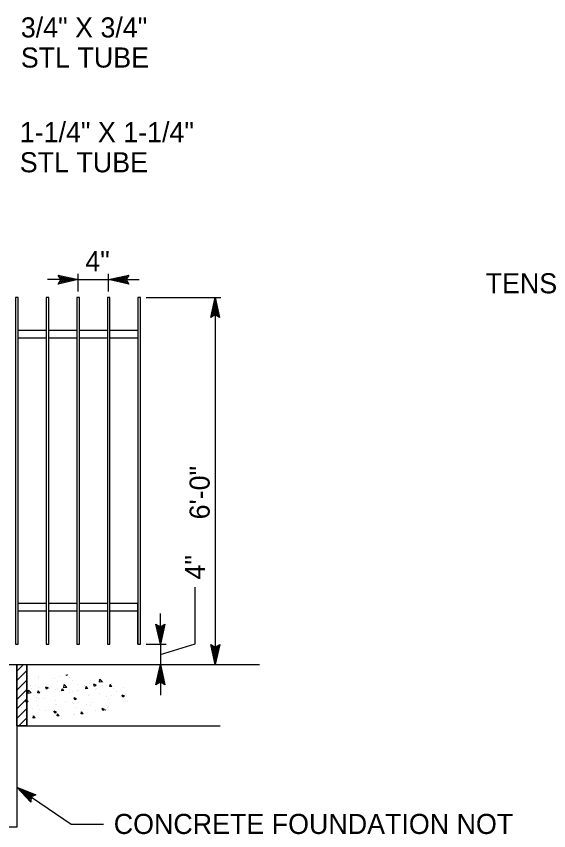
# Model space of a CAD drawing. Extents: x 6710407 to 6714861, y 1868090 to 1871317.
# Drawn here: x 6711831.3 to 6711990.6, y 1869738.6 to 1869981.9 of the extents above; entities that cross this region are included whole.
import ezdxf

# ---------------------------------------------------------------- set-up
doc = ezdxf.new("R2010")
doc.units = 0
for name, color, linetype in [('Erosion C (Lv35)', 7, 'Continuous'), ('G-MARK', 7, 'Continuous'), ('G-TEXT', 7, 'Continuous'), ('Nongeo Data(60)', 7, 'Continuous')]:
    doc.layers.add(name, color=color, linetype=linetype)

# ---------------------------------------------------------------- blocks, each defined once
blk = doc.blocks.new('SC8415')
at = {"layer": 'Erosion C (Lv35)'}
for p, q in [((-1.70669, 1.76754), (-1.7059, 1.76836)), ((-1.70579, 1.7674), (-1.7059, 1.76836)), ((-1.70304, 1.76795), (-1.70304, 1.76795)), ((-1.6975, 1.7679), (-1.6975, 1.7679)), ((-1.69662, 1.7688), (-1.69662, 1.7688)), ((-1.69606, 1.76963), (-1.69579, 1.76945)), ((-1.69579, 1.76945), (-1.69573, 1.76963)), ((-1.69408, 1.76913), (-1.69408, 1.76913)), ((-1.69309, 1.7676), (-1.69309, 1.7676)), ((-1.69228, 1.76861), (-1.69228, 1.76861)), ((-1.68716, 1.76862), (-1.68716, 1.76862)), ((-1.68715, 1.76926), (-1.68715, 1.76926)), ((-1.71312, 1.76577), (-1.71312, 1.76577)), ((-1.71, 1.76543), (-1.71, 1.76543)), ((-1.70955, 1.76614), (-1.70906, 1.76672)), ((-1.70955, 1.76614), (-1.70894, 1.76608)), ((-1.70943, 1.76711), (-1.70943, 1.76711)), ((-1.70894, 1.76609), (-1.70906, 1.76672)), ((-1.70791, 1.76649), (-1.70791, 1.76649)), ((-1.70689, 1.76745), (-1.70689, 1.76745)), ((-1.70672, 1.76656), (-1.70672, 1.76656)), ((-1.70669, 1.76754), (-1.70579, 1.7674)), ((-1.70494, 1.76557), (-1.70494, 1.76557)), ((-1.70484, 1.76651), (-1.70412, 1.76679)), ((-1.70484, 1.76651), (-1.70433, 1.76617)), ((-1.70458, 1.7652), (-1.70458, 1.7652)), ((-1.70433, 1.76617), (-1.70412, 1.76679)), ((-1.70278, 1.76714), (-1.70278, 1.76714)), ((-1.70226, 1.7655), (-1.70177, 1.76608)), ((-1.70226, 1.7655), (-1.70165, 1.76545)), ((-1.70165, 1.76545), (-1.70177, 1.76609)), ((-1.7013, 1.76633), (-1.7013, 1.76633)), ((-1.69901, 1.76659), (-1.69901, 1.76659)), ((-1.69675, 1.76513), (-1.69675, 1.76513)), ((-1.69588, 1.7661), (-1.69588, 1.7661)), ((-1.69585, 1.76586), (-1.69506, 1.76668)), ((-1.69585, 1.76586), (-1.69494, 1.76572)), ((-1.69494, 1.76572), (-1.69506, 1.76668)), ((-1.69497, 1.76486), (-1.69449, 1.76545)), ((-1.69437, 1.76481), (-1.69448, 1.76545)), ((-1.6929, 1.76563), (-1.6929, 1.76563)), ((-1.69241, 1.76523), (-1.69241, 1.76523)), ((-1.69065, 1.76537), (-1.69065, 1.76537)), ((-1.69045, 1.76587), (-1.69045, 1.76587)), ((-1.69023, 1.7657), (-1.68952, 1.76597)), ((-1.69023, 1.7657), (-1.68973, 1.76536)), ((-1.68973, 1.76536), (-1.68952, 1.76597)), ((-1.68727, 1.76588), (-1.68727, 1.76588)), ((-1.68649, 1.76648), (-1.68649, 1.76648)), ((-1.68503, 1.76565), (-1.68503, 1.76565)), ((-1.68473, 1.76639), (-1.68473, 1.76639)), ((-1.68394, 1.76681), (-1.68394, 1.76681)), ((-1.682, 1.76664), (-1.682, 1.76664)), ((-1.71337, 1.76324), (-1.71266, 1.76351)), ((-1.71337, 1.76324), (-1.71287, 1.7629)), ((-1.71287, 1.7629), (-1.71266, 1.76351)), ((-1.7121, 1.7631), (-1.7121, 1.7631)), ((-1.71086, 1.76455), (-1.71086, 1.76455)), ((-1.70956, 1.76344), (-1.70956, 1.76344)), ((-1.70803, 1.7631), (-1.70803, 1.7631)), ((-1.70571, 1.76395), (-1.70571, 1.76395)), ((-1.7029, 1.76375), (-1.7029, 1.76375)), ((-1.7025, 1.76334), (-1.7025, 1.76334)), ((-1.6993, 1.76479), (-1.6993, 1.76479)), ((-1.69916, 1.76497), (-1.69916, 1.76497)), ((-1.69877, 1.76242), (-1.69806, 1.7627)), ((-1.69826, 1.76208), (-1.69806, 1.7627)), ((-1.69762, 1.76452), (-1.69762, 1.76452)), ((-1.69658, 1.76435), (-1.69658, 1.76435)), ((-1.69497, 1.76486), (-1.69437, 1.76481)), ((-1.69373, 1.76474), (-1.69373, 1.76474)), ((-1.68831, 1.76451), (-1.68831, 1.76451)), ((-1.68769, 1.76423), (-1.6872, 1.76481)), ((-1.68769, 1.76423), (-1.68708, 1.76417)), ((-1.68708, 1.76417), (-1.6872, 1.76481)), ((-1.68662, 1.7628), (-1.68662, 1.7628)), ((-1.685, 1.76418), (-1.68421, 1.765)), ((-1.685, 1.76418), (-1.6841, 1.76404)), ((-1.6841, 1.76404), (-1.68421, 1.765)), ((-1.68289, 1.76428), (-1.68289, 1.76428)), ((-1.68277, 1.76331), (-1.68277, 1.76331)), ((-1.71417, 1.76163), (-1.71417, 1.76163)), ((-1.71325, 1.76239), (-1.71325, 1.76239)), ((-1.70874, 1.7614), (-1.70874, 1.7614)), ((-1.70843, 1.76232), (-1.70843, 1.76232)), ((-1.70332, 1.76117), (-1.70332, 1.76117)), ((-1.70302, 1.76037), (-1.70302, 1.76037)), ((-1.70197, 1.76078), (-1.70197, 1.76078)), ((-1.69943, 1.76112), (-1.69943, 1.76112)), ((-1.69877, 1.76242), (-1.69827, 1.76208)), ((-1.6979, 1.76094), (-1.6979, 1.76094)), ((-1.69775, 1.76113), (-1.69775, 1.76113)), ((-1.69558, 1.76162), (-1.69558, 1.76162)), ((-1.6927, 1.7608), (-1.6927, 1.7608)), ((-1.69253, 1.76185), (-1.69253, 1.76185)), ((-1.69247, 1.76071), (-1.69247, 1.76071)), ((-1.68916, 1.76247), (-1.68916, 1.76247)), ((-1.6874, 1.7625), (-1.6874, 1.7625)), ((-1.68705, 1.76048), (-1.68705, 1.76048)), ((-1.68677, 1.76182), (-1.68677, 1.76182)), ((-1.68417, 1.76161), (-1.68346, 1.76188)), ((-1.68417, 1.76161), (-1.68366, 1.76127)), ((-1.68366, 1.76127), (-1.68346, 1.76188)), ((-1.70839, 1.75994), (-1.70839, 1.75994)), ((-1.70815, 1.75972), (-1.70815, 1.75972)), ((-1.70775, 1.75896), (-1.70765, 1.75908)), ((-1.70762, 1.7589), (-1.70765, 1.75908)), ((-1.70731, 1.75915), (-1.7066, 1.75942)), ((-1.70731, 1.75915), (-1.7068, 1.75881)), ((-1.7068, 1.75881), (-1.7066, 1.75942)), ((-1.70455, 1.75876), (-1.70455, 1.75876)), ((-1.70085, 1.75786), (-1.70036, 1.75844)), ((-1.70085, 1.75786), (-1.70025, 1.7578)), ((-1.70024, 1.75781), (-1.70036, 1.75844)), ((-1.69862, 1.75978), (-1.69862, 1.75978)), ((-1.69787, 1.75775), (-1.69787, 1.75775)), ((-1.69357, 1.75722), (-1.69308, 1.7578)), ((-1.69296, 1.75717), (-1.69307, 1.75781)), ((-1.69271, 1.75833), (-1.692, 1.75861)), ((-1.69271, 1.75833), (-1.6922, 1.75799)), ((-1.69265, 1.75847), (-1.69265, 1.75847)), ((-1.6922, 1.75799), (-1.69199, 1.75861)), ((-1.69183, 1.75846), (-1.69183, 1.75846)), ((-1.68929, 1.7588), (-1.68929, 1.7588)), ((-1.68752, 1.75912), (-1.68752, 1.75912)), ((-1.68544, 1.7593), (-1.68544, 1.7593)), ((-1.68224, 1.75988), (-1.68224, 1.75988)), ((-1.69825, 1.75762), (-1.69825, 1.75762)), ((-1.69357, 1.75722), (-1.69296, 1.75717)), ((-1.68628, 1.75658), (-1.68579, 1.75717)), ((-1.68628, 1.75658), (-1.68567, 1.75653)), ((-1.68567, 1.75653), (-1.68579, 1.75717))]:
    blk.add_line(p, q, dxfattribs=at)

msp = doc.modelspace()

# ---------------------------------------------------------------- linework, layer by layer
at = {"layer": 'G-MARK'}
for p, q in [((6711849.81, 1869899.67), (6711849.81, 1869904.96)), ((6711858.95, 1869899.67), (6711858.95, 1869904.96)), ((6711849.81, 1869903.25), (6711840.67, 1869903.25)), ((6711849.81, 1869903.25), (6711858.95, 1869903.25)), ((6711858.95, 1869903.25), (6711868.1, 1869903.25)), ((6711870.19, 1869897.95), (6711892.54, 1869897.95)), ((6711890.82, 1869897.95), (6711890.82, 1869788.23)), ((6711884.84, 1869794.4), (6711884.84, 1869811.39)), ((6711874.43, 1869794.32), (6711874.43, 1869803.47)), ((6711870.19, 1869794.32), (6711876.14, 1869794.32)), ((6711874.43, 1869791.27), (6711884.84, 1869794.4)), ((6711874.43, 1869794.32), (6711874.43, 1869788.23)), ((6711874.43, 1869788.23), (6711874.43, 1869779.08)), ((6711831.52, 1869751.65), (6711847.73, 1869740.59)), ((6711847.73, 1869740.59), (6711857.4, 1869740.59))]:
    msp.add_line(p, q, dxfattribs=at)
at = {"layer": 'G-TEXT'}
for p, q in [((6711844.61, 1869903.25), (6711843.81, 1869904.59)), ((6711843.81, 1869904.59), (6711843.81, 1869904.59)), ((6711843.81, 1869904.59), (6711849.81, 1869903.25)), ((6711858.95, 1869903.25), (6711864.95, 1869904.58)), ((6711864.95, 1869904.58), (6711864.15, 1869903.25)), ((6711864.95, 1869904.58), (6711864.95, 1869904.58)), ((6711849.81, 1869903.25), (6711843.81, 1869901.92)), ((6711843.81, 1869901.92), (6711844.61, 1869903.25)), ((6711843.81, 1869901.92), (6711843.81, 1869901.92)), ((6711844.03, 1869904.23), (6711848.43, 1869903.25)), ((6711848.42, 1869903.25), (6711844.04, 1869902.28)), ((6711847.05, 1869903.25), (6711844.22, 1869902.62)), ((6711844.26, 1869903.87), (6711847.05, 1869903.25)), ((6711844.44, 1869903.53), (6711845.67, 1869903.25)), ((6711845.67, 1869903.25), (6711844.46, 1869902.98)), ((6711849.81, 1869903.25), (6711849.81, 1869903.25)), ((6711864.95, 1869901.91), (6711858.95, 1869903.25)), ((6711858.95, 1869903.25), (6711858.95, 1869903.25)), ((6711864.74, 1869902.26), (6711860.33, 1869903.25)), ((6711860.35, 1869903.25), (6711864.72, 1869904.22)), ((6711861.72, 1869903.25), (6711864.54, 1869903.87)), ((6711864.5, 1869902.62), (6711861.72, 1869903.25)), ((6711863.1, 1869903.25), (6711864.31, 1869903.51)), ((6711864.33, 1869902.97), (6711863.1, 1869903.25)), ((6711864.15, 1869903.25), (6711864.95, 1869901.91)), ((6711864.95, 1869901.91), (6711864.95, 1869901.91)), ((6711889.48, 1869891.95), (6711890.82, 1869897.95)), ((6711890.82, 1869897.95), (6711890.82, 1869897.95)), ((6711890.82, 1869897.95), (6711892.15, 1869891.95)), ((6711889.84, 1869892.17), (6711890.82, 1869896.57)), ((6711890.2, 1869892.4), (6711890.82, 1869895.19)), ((6711890.82, 1869895.19), (6711891.45, 1869892.37)), ((6711890.83, 1869896.56), (6711891.79, 1869892.19)), ((6711890.82, 1869892.75), (6711889.48, 1869891.95)), ((6711890.55, 1869892.58), (6711890.82, 1869893.81)), ((6711890.82, 1869893.81), (6711891.09, 1869892.6)), ((6711892.15, 1869891.95), (6711890.82, 1869892.75)), ((6711889.48, 1869891.95), (6711889.48, 1869891.95)), ((6711892.15, 1869891.95), (6711892.15, 1869891.95)), ((6711874.43, 1869794.32), (6711873.1, 1869800.32)), ((6711873.1, 1869800.32), (6711873.1, 1869800.32)), ((6711873.1, 1869800.32), (6711874.43, 1869799.52)), ((6711874.43, 1869795.71), (6711873.46, 1869800.09)), ((6711874.43, 1869797.08), (6711873.8, 1869799.91)), ((6711874.43, 1869798.47), (6711874.16, 1869799.67)), ((6711874.43, 1869799.52), (6711875.77, 1869800.32)), ((6711875.77, 1869800.32), (6711874.43, 1869794.32)), ((6711875.41, 1869800.1), (6711874.43, 1869795.7)), ((6711875.05, 1869799.87), (6711874.43, 1869797.08)), ((6711874.71, 1869799.69), (6711874.43, 1869798.47)), ((6711875.77, 1869800.32), (6711875.77, 1869800.32)), ((6711874.43, 1869794.32), (6711874.43, 1869794.32)), ((6711890.82, 1869788.23), (6711889.49, 1869794.23)), ((6711889.49, 1869794.23), (6711889.49, 1869794.23)), ((6711889.49, 1869794.23), (6711890.82, 1869793.43)), ((6711890.82, 1869789.62), (6711889.85, 1869793.99)), ((6711890.83, 1869790.99), (6711890.2, 1869793.81)), ((6711890.83, 1869792.37), (6711890.56, 1869793.58)), ((6711890.82, 1869793.43), (6711892.16, 1869794.23)), ((6711892.16, 1869794.23), (6711890.82, 1869788.23)), ((6711891.81, 1869794.01), (6711890.82, 1869789.61)), ((6711891.45, 1869793.77), (6711890.83, 1869790.99)), ((6711891.1, 1869793.6), (6711890.83, 1869792.37)), ((6711892.16, 1869794.23), (6711892.16, 1869794.23)), ((6711873.09, 1869782.23), (6711874.43, 1869788.23)), ((6711874.43, 1869788.23), (6711874.43, 1869788.23)), ((6711874.43, 1869788.23), (6711875.76, 1869782.23)), ((6711890.82, 1869788.23), (6711890.82, 1869788.23)), ((6711873.44, 1869782.44), (6711874.43, 1869786.85)), ((6711873.8, 1869782.68), (6711874.43, 1869785.46)), ((6711874.43, 1869786.83), (6711875.4, 1869782.46)), ((6711874.43, 1869785.46), (6711875.05, 1869782.64)), ((6711874.43, 1869783.03), (6711873.09, 1869782.23)), ((6711874.15, 1869782.85), (6711874.43, 1869784.08)), ((6711874.43, 1869784.08), (6711874.69, 1869782.87)), ((6711875.76, 1869782.23), (6711874.43, 1869783.03)), ((6711873.09, 1869782.23), (6711873.09, 1869782.23)), ((6711875.76, 1869782.23), (6711875.76, 1869782.23)), ((6711835.71, 1869747.14), (6711831.52, 1869751.65)), ((6711831.52, 1869751.65), (6711831.52, 1869751.65)), ((6711831.52, 1869751.65), (6711837.22, 1869749.34)), ((6711835.73, 1869747.56), (6711832.66, 1869750.87)), ((6711832.67, 1869750.86), (6711836.82, 1869749.18)), ((6711835.74, 1869747.99), (6711833.8, 1869750.08)), ((6711833.8, 1869750.08), (6711836.48, 1869749)), ((6711835.79, 1869748.37), (6711834.93, 1869749.3)), ((6711834.93, 1869749.3), (6711836.08, 1869748.83)), ((6711835.81, 1869748.7), (6711835.71, 1869747.14)), ((6711837.22, 1869749.34), (6711835.81, 1869748.7)), ((6711837.22, 1869749.34), (6711837.22, 1869749.34)), ((6711835.71, 1869747.14), (6711835.71, 1869747.14))]:
    msp.add_line(p, q, dxfattribs=at)
at = {"layer": 'Nongeo Data(60)'}
for p, q in [((6711858.95, 1869903.25), (6711858.95, 1869903.25)), ((6711849.81, 1869897.95), (6711849.81, 1869897.95)), ((6711858.95, 1869897.95), (6711858.95, 1869897.95)), ((6711868.48, 1869897.95), (6711868.48, 1869897.95)), ((6711840.29, 1869888.05), (6711831.9, 1869888.05)), ((6711849.43, 1869888.05), (6711841.05, 1869888.05)), ((6711858.57, 1869888.05), (6711850.19, 1869888.05)), ((6711867.72, 1869888.05), (6711859.34, 1869888.05)), ((6711840.29, 1869885.76), (6711831.9, 1869885.76)), ((6711849.43, 1869885.76), (6711841.05, 1869885.76)), ((6711858.57, 1869885.76), (6711850.19, 1869885.76)), ((6711867.72, 1869885.76), (6711859.34, 1869885.76)), ((6711840.29, 1869806.51), (6711831.9, 1869806.51)), ((6711849.43, 1869806.51), (6711841.05, 1869806.51)), ((6711858.57, 1869806.51), (6711850.19, 1869806.51)), ((6711867.72, 1869806.51), (6711859.34, 1869806.51)), ((6711867.72, 1869794.32), (6711867.72, 1869806.51)), ((6711840.29, 1869804.23), (6711831.9, 1869804.23)), ((6711849.43, 1869804.23), (6711841.05, 1869804.23)), ((6711858.57, 1869804.23), (6711850.19, 1869804.23)), ((6711867.72, 1869804.23), (6711859.34, 1869804.23)), ((6711868.48, 1869794.32), (6711868.48, 1869794.32)), ((6711576.51, 1869788.23), (6711904.03, 1869788.23)), ((6711813.23, 1869788.23), (6711831.52, 1869788.23)), ((6711831.52, 1869788.23), (6711831.52, 1869739.65)), ((6711831.52, 1869786.29), (6711833.46, 1869788.23)), ((6711834.52, 1869769.94), (6711834.52, 1869788.23)), ((6711868.48, 1869788.23), (6711868.48, 1869788.23)), ((6711868.48, 1869788.23), (6711868.48, 1869788.23)), ((6711870.19, 1869788.23), (6711892.54, 1869788.23)), ((6711870.19, 1869788.23), (6711876.14, 1869788.23)), ((6711874.43, 1869788.23), (6711874.43, 1869788.23)), ((6711890.82, 1869788.23), (6711890.82, 1869788.23)), ((6711831.52, 1869783.46), (6711834.52, 1869786.46)), ((6711831.52, 1869780.63), (6711834.52, 1869783.63)), ((6711831.52, 1869777.8), (6711834.52, 1869780.8)), ((6711831.52, 1869774.97), (6711834.52, 1869777.97)), ((6711831.52, 1869772.15), (6711834.52, 1869775.15)), ((6711832.14, 1869769.94), (6711834.52, 1869772.32)), ((6711831.52, 1869769.94), (6711892.31, 1869769.94)), ((6711831.52, 1869739.65), (6711813.23, 1869739.65))]:
    msp.add_line(p, q, dxfattribs=at)
for points in [[(6711831.14, 1869794.32), (6711831.9, 1869794.32), (6711831.9, 1869897.95), (6711831.14, 1869897.95)], [(6711840.29, 1869794.32), (6711841.05, 1869794.32), (6711841.05, 1869897.95), (6711840.29, 1869897.95)], [(6711849.43, 1869794.32), (6711850.19, 1869794.32), (6711850.19, 1869897.95), (6711849.43, 1869897.95)], [(6711858.57, 1869794.32), (6711859.34, 1869794.32), (6711859.34, 1869897.95), (6711858.57, 1869897.95)], [(6711867.72, 1869794.32), (6711868.48, 1869794.32), (6711868.48, 1869897.95), (6711867.72, 1869897.95)], [(6711831.52, 1869788.23), (6711834.52, 1869788.23), (6711834.52, 1869769.94), (6711831.52, 1869769.94)]]:
    msp.add_lwpolyline(points, close=True, dxfattribs=at)

# ---------------------------------------------------------------- block references
at = {"layer": 'Nongeo Data(60)', "xscale": 984.251968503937, "yscale": -984.251968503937, "rotation": 180}
msp.add_blockref('SC8415', (6710177.28, 1868043.38), dxfattribs=at)

# ---------------------------------------------------------------- texts
at = {"layer": 'Nongeo Data(60)'}
for s, p in [('3/4" X 3/4"', (6711832.69, 1869975.6)), ('STL TUBE', (6711832.69, 1869966.6)), ('1-1/4" X 1-1/4"', (6711832.38, 1869944.31)), ('STL TUBE', (6711832.38, 1869935.31)), ('4"', (6711851.97, 1869905.76)), ('TENSION CABLE, TYP', (6711971.69, 1869899.15)), ('CONCRETE FOUNDATION NOT', (6711860.48, 1869737.63))]:
    msp.add_text(s, height=6, dxfattribs=at).set_placement(p)
for s, p in [('6\'-0"', (6711889.16, 1869831.62)), ('4"', (6711887.75, 1869813.65))]:
    msp.add_text(s, height=6, rotation=90, dxfattribs=at).set_placement(p)

doc.saveas('drawing.dxf')
